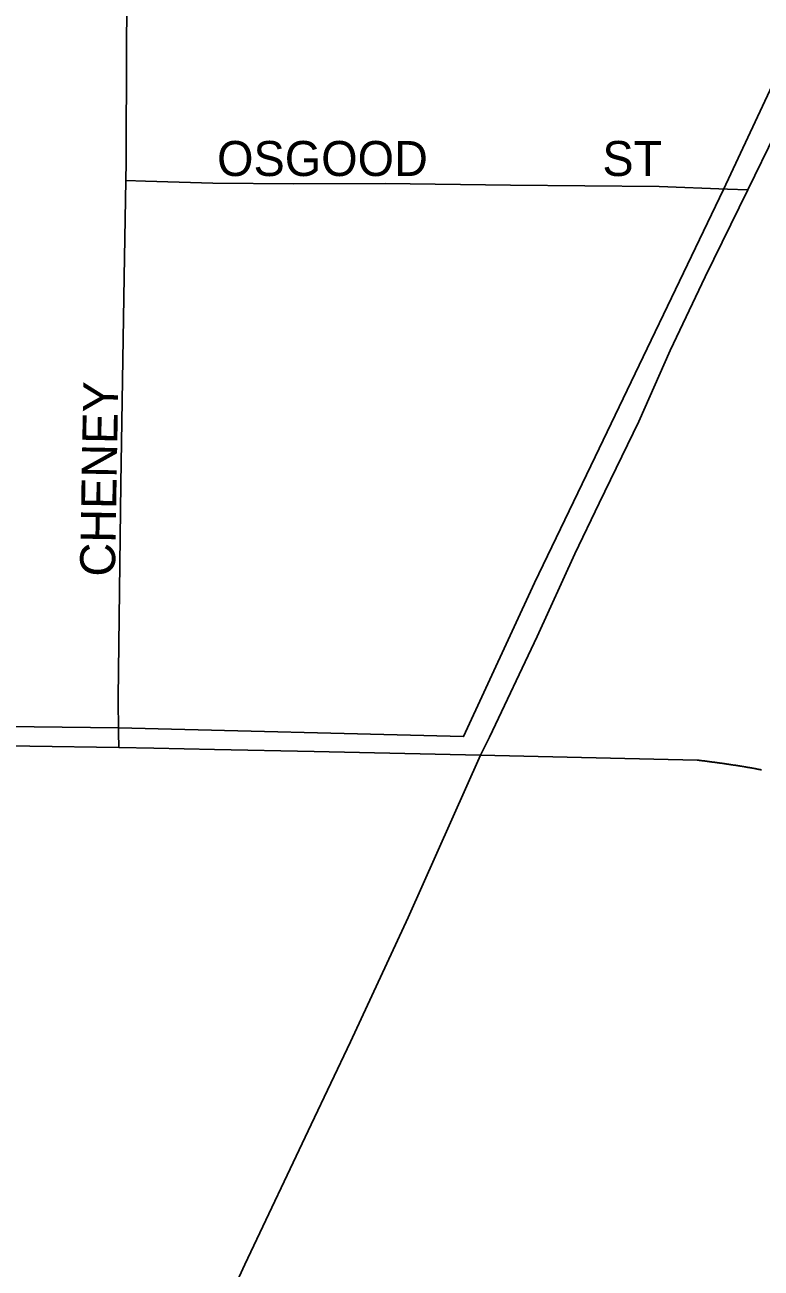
# Model space of a CAD drawing. Extents: x -9.1 to 34, y -3.1 to 22.
# Drawn here: x 4.6822 to 4.8813, y 18.1315 to 18.4677 of the extents above; entities that cross this region are included whole.
import ezdxf

# ---------------------------------------------------------------- set-up
doc = ezdxf.new("R2010")
doc.units = 0
for name, color, linetype in [('GM_X_City_Street', 7, 'Continuous'), ('GM_X_City_Street_Text', 7, 'Continuous'), ('GM_X_Corporation', 7, 'Continuous'), ('GM_X_County_Road', 7, 'Continuous'), ('GM_X_State_Route', 7, 'Continuous')]:
    doc.layers.add(name, color=color, linetype=linetype)

msp = doc.modelspace()

# ---------------------------------------------------------------- linework, layer by layer
at = {"layer": 'GM_X_City_Street'}
for points in [[(4.70955, 18.4257), (4.70964, 18.43064), (4.70974, 18.46172), (4.70999, 18.49453)], [(4.70758, 18.27232), (4.70755, 18.27635), (4.70747, 18.28571), (4.70814, 18.34366), (4.70906, 18.39959), (4.70955, 18.4257)], [(4.70955, 18.4257), (4.71487, 18.42551), (4.73304, 18.42492), (4.7549, 18.42475), (4.7796, 18.42483), (4.81355, 18.42442), (4.85368, 18.42401), (4.87219, 18.42332), (4.87767, 18.42312)]]:
    msp.add_lwpolyline(points, dxfattribs=at)
at = {"layer": 'GM_X_Corporation'}
msp.add_lwpolyline([(4.48709, 18.28022), (4.70754, 18.2776), (4.80082, 18.27528), (4.82, 18.31687), (4.83638, 18.35097), (4.87109, 18.42324), (4.90339, 18.49229), (4.93534, 18.5608), (4.96194, 18.61779), (4.96775, 18.61559), (5.16013, 18.52629), (5.15861, 18.26589), (5.2044, 18.26599), (5.22711, 18.26576), (5.2741, 18.26585), (5.53122, 18.26459)], dxfattribs=at)
at = {"layer": 'GM_X_County_Road'}
for points in [[(4.47636, 18.27506), (4.48649, 18.27499), (4.49514, 18.27475), (4.51059, 18.27469), (4.54145, 18.27456), (4.57848, 18.27416), (4.62477, 18.27351), (4.67109, 18.27284), (4.68357, 18.27266)], [(4.68357, 18.27266), (4.70758, 18.27232)], [(4.70758, 18.27232), (4.71709, 18.27218), (4.73353, 18.27181)], [(4.73353, 18.27181), (4.7604, 18.2712), (4.80539, 18.27022)], [(4.80539, 18.27022), (4.86397, 18.26892), (4.8642, 18.26889), (4.86442, 18.26886), (4.86464, 18.26884), (4.86487, 18.26881), (4.86508, 18.26878), (4.8653, 18.26876), (4.86552, 18.26873), (4.86574, 18.2687), (4.86595, 18.26868), (4.86617, 18.26865), (4.86638, 18.26862), (4.86659, 18.26859), (4.8668, 18.26857), (4.86702, 18.26854), (4.86723, 18.26851), (4.86744, 18.26849), (4.86764, 18.26846), (4.86785, 18.26843), (4.86806, 18.2684), (4.86826, 18.26838), (4.86847, 18.26835), (4.86867, 18.26832), (4.86888, 18.2683), (4.86908, 18.26827), (4.86928, 18.26824), (4.86949, 18.26822), (4.86969, 18.26818), (4.86989, 18.26816), (4.87009, 18.26813), (4.87028, 18.2681), (4.87048, 18.26807), (4.87068, 18.26805), (4.87087, 18.26802), (4.87107, 18.26799), (4.87127, 18.26797), (4.87146, 18.26794), (4.87166, 18.2679), (4.87185, 18.26788), (4.87204, 18.26785), (4.87224, 18.26782), (4.87243, 18.26779), (4.87262, 18.26777), (4.87281, 18.26774), (4.873, 18.26771), (4.87319, 18.26768), (4.87338, 18.26765), (4.87356, 18.26763), (4.87376, 18.26759), (4.87394, 18.26756), (4.87413, 18.26754), (4.87432, 18.26751), (4.8745, 18.26748), (4.87468, 18.26745), (4.87487, 18.26742), (4.87506, 18.26739), (4.87524, 18.26736), (4.87542, 18.26733), (4.8756, 18.2673), (4.87579, 18.26727), (4.87588, 18.26726), (4.87597, 18.26724), (4.87606, 18.26723), (4.87615, 18.26721), (4.87624, 18.2672), (4.87633, 18.26718), (4.87642, 18.26717), (4.87651, 18.26715), (4.8766, 18.26714), (4.87669, 18.26712), (4.87685, 18.2671), (4.87702, 18.26707), (4.87718, 18.26704), (4.87734, 18.26701), (4.8775, 18.26699), (4.87767, 18.26695), (4.87783, 18.26693), (4.878, 18.2669), (4.87816, 18.26687), (4.87833, 18.26684), (4.8785, 18.26681), (4.87866, 18.26678), (4.87883, 18.26675), (4.879, 18.26672), (4.87916, 18.26669), (4.87933, 18.26666), (4.8795, 18.26663), (4.87967, 18.2666), (4.87983, 18.26657), (4.88, 18.26654), (4.88017, 18.2665), (4.88034, 18.26647), (4.88051, 18.26644), (4.88068, 18.26641), (4.88085, 18.26638), (4.88102, 18.26634), (4.88119, 18.26631), (4.88136, 18.26628)]]:
    msp.add_lwpolyline(points, dxfattribs=at)
at = {"layer": 'GM_X_State_Route'}
for points in [[(4.87767, 18.42312), (4.88518, 18.43842), (4.89813, 18.46653), (4.91007, 18.49218), (4.92815, 18.53102), (4.94177, 18.56081), (4.94745, 18.5732), (4.96775, 18.61559)], [(4.75961, 18.17035), (4.77022, 18.19271), (4.78586, 18.22634), (4.80539, 18.27022), (4.80782, 18.27515), (4.82076, 18.30238), (4.83086, 18.3247), (4.83744, 18.33842), (4.84816, 18.36047), (4.85666, 18.37972), (4.86613, 18.39959), (4.87767, 18.42312)], [(4.5258, 17.67653), (4.52779, 17.68055), (4.56353, 17.75296), (4.57223, 17.77054), (4.58282, 17.79193), (4.60853, 17.84506), (4.63495, 17.90128), (4.66367, 17.96327), (4.68209, 18.00267), (4.70801, 18.05914), (4.71332, 18.07072), (4.74167, 18.13255), (4.75961, 18.17035)]]:
    msp.add_lwpolyline(points, dxfattribs=at)

# ---------------------------------------------------------------- texts
at = {"layer": 'GM_X_City_Street_Text'}
for s, rotation, p in [('OSGOOD', 0, (4.73418, 18.42687)), ('ST', 0, (4.83835, 18.42687)), ('CHENEY', 88.9775, (4.70656, 18.31846))]:
    msp.add_text(s, height=0.00947, rotation=rotation, dxfattribs=at).set_placement(p)

doc.saveas('drawing.dxf')
